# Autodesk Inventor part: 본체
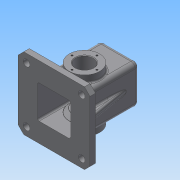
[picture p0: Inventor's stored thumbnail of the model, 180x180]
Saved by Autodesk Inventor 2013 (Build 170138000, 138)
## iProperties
Created: 2016-02
Part Number: 본체
Material: Generic
Document SubType Name: Modeling
Designer: Administrator
Density: 1 g/cm^3
Author: Administrator
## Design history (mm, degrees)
sketch "스케치1"
  geometry: L1 (-35, -35)-(35, -35); L2 (35, -35)-(35, 35); L3 (35, 35)-(-35, 35); L4 (-35, 35)-(-35, -35); L5 (-35, -35)-(35, 35); L6 (35, -35)-(-35, 35); 1 further point
  constraints: 12 end point, 2 midpoint, 2 parallel, 2 perpendicular, 1 horizontal
  dimensions: "d0" = 70 distance of L2.end L3.end
extrude "돌출1" new body sketch "스케치1" distance "d2" = 120; taper "d3" = 0 deg
fillet "모깎기1" dims "d5" = 8
fillet "모깎기2" dims "d6" = 8
feature "쉘1" dims "d7" = 5
sketch "스케치2"
  geometry: L1 (-65, -65)-(65, -65); L2 (65, -65)-(65, 65); L3 (65, 65)-(-65, 65); L4 (-65, 65)-(-65, -65); L5 (-65, -65)-(65, 65); L6 (65, -65)-(-65, 65); L7 (30, -27)-(30, 27) reference; L8 (27, 30)-(-27, 30) reference; L9 (-30, 27)-(-30, -27) reference; L10 (-27, -30)-(27, -30) reference; L11 (27, -35)-(-27, -35) reference; L12 (-35, -27)-(-35, 27) reference; L13 (-27, 35)-(27, 35) reference; L14 (35, 27)-(35, -27) reference; A1 r 3 centre (27, -27) between (27, -30) and (30, -27) reference; A2 r 3 centre (27, 27) between (30, 27) and (27, 30) reference; A3 r 3 centre (-27, 27) between (-27, 30) and (-30, 27) reference; A4 r 3 centre (-27, -27) between (-30, -27) and (-27, -30) reference; A5 r 8 centre (27, -27) between (27, -35) and (35, -27) reference; A6 r 8 centre (-27, -27) between (-35, -27) and (-27, -35) reference; A7 r 8 centre (-27, 27) between (-27, 35) and (-35, 27) reference; A8 r 8 centre (27, 27) between (35, 27) and (27, 35) reference; 1 further point
  constraints: 12 end point, 2 midpoint, 2 parallel, 2 perpendicular, 1 horizontal
  dimensions: "d8" = 130 distance of L2.end L3.end
extrude "돌출2" join sketch "스케치2" distance "d10" = 10; taper "d11" = 0 deg
sketch "스케치3"
  geometry: L1 (65, 65)-(-65, 65) reference; L2 (65, -65)-(65, 65) reference; 3 further points
  constraints: 1 vertical alignment
  dimensions: "d12" = 100 distance of point (50, 50) point (50, -50); "d14" = 15 distance from line of L1 point (50, 50); "d15" = 15 distance from line of point (50, 50) L2
hole "구멍1" sketch "스케치3" at (50, -50), (50, 50) diameter "d16" = 12; stored, may be unused: countersink angle "d20" = 90 deg, drill point angle "d22" = 0 deg; dims "d17" = 6, "d18" = 4, "d19" = 2, "d21" = 8
chamfer "모따기1" distance "d23" = 10; stored, may be unused: second distance "d24" = 2, angle "d25" = 45 deg
node "작업 평면1"
sketch "스케치5"
  geometry: L1 (-27, 0)-(27, 0) reference; C1 r 27.5 at (0, 55); 1 further point
  constraints: 1 centre point, 1 midpoint, 1 vertical alignment
  dimensions: "d26" = 55 diameter of C1; "d29" = 55 distance of point (0, 0) C1.centre
extrude "돌출3" join sketch "스케치5" stored distance "d30" = 10; taper "d31" = 0 deg
sketch "스케치6"
  geometry: C1 r 27.5 at (27, 55) reference; C2 r 27.5 at (27, 55); 1 further point
  constraints: 1 centre point, 1 coincident
  dimensions: "d32" = 55 diameter of C2
extrude "돌출4" join sketch "스케치6" distance "d33" = 7; taper "d34" = -45 deg
hole "구멍2" diameter "d37" = 32; stored, may be unused: countersink angle "d41" = 90 deg, drill point angle "d43" = 0 deg; dims "d35" = 10, "d36" = 10, "d38" = 6, "d39" = 4, "d40" = 2, "d42" = 8
sketch "스케치7"
  geometry: C1 r 16 at (0, 0) reference; 2 further points
  constraints: 1 vertical alignment
  dimensions: "d44" = 22.5 distance of C1.centre point (0, 22.5)
hole "구멍3" sketch "스케치7" at (0, 22.5) diameter "d45" = 3.242; stored, may be unused: countersink angle "d49" = 90 deg, drill point angle "d51" = 118 deg; dims "d46" = 8, "d47" = 4, "d48" = 2, "d50" = 10
sketch "스케치8"
  geometry: C1 r 20 at (0, 0); 1 further point
  constraints: 1 centre point, 1 coincident
  dimensions: "d56" = 40 diameter of C1
extrude "돌출5" join sketch "스케치8" distance "d57" = 10; taper "d58" = -10 deg
hole "구멍4" diameter "d61" = 21; stored, may be unused: countersink angle "d65" = 90 deg, drill point angle "d67" = 0 deg; dims "d59" = 10, "d60" = 10, "d62" = 8, "d63" = 28, "d64" = 4, "d66" = 10
chamfer "모따기2" distance "d68" = 1; stored, may be unused: second distance "d69" = 2, angle "d70" = 45 deg
sketch "스케치9"
  geometry: L1 (27, 115)-(10.5, 115) reference; L2 (10.5, 115)-(10.5, 126) reference; L3 (10.5, 126)-(14, 126) reference; L4 (14, 126)-(14, 130) reference; L5 (14, 130)-(18.237, 130) reference; L6 (18.237, 130)-(20, 120) reference; L7 (20, 120)-(27, 120) reference; L8 (35, 112)-(35, 10) reference; L9 (35, 10)-(65, 10) reference; L10 (65, 10)-(65, 0) reference; L11 (65, 0)-(30, 0) reference; L12 (30, 0)-(30, 112) reference; L13 (-27, 120)-(-20, 120) reference; L14 (-20, 120)-(-18.237, 130) reference; L15 (-18.237, 130)-(-14, 130) reference; L16 (-14, 130)-(-14, 126) reference; L17 (-14, 126)-(-10.5, 126) reference; L18 (-10.5, 126)-(-10.5, 115) reference; L19 (-10.5, 115)-(-27, 115) reference; L20 (-30, 112)-(-30, 0) reference; L21 (-30, 0)-(-65, 0) reference; L22 (-65, 0)-(-65, 10) reference; L23 (-65, 10)-(-35, 10) reference; L24 (-35, 10)-(-35, 112) reference; L25 (35, 95.069)-(50, 10); A1 r 3 centre (27, 112) between (30, 112) and (27, 115) reference; A2 r 8 centre (27, 112) between (35, 112) and (27, 120) reference; A3 r 8 centre (-27, 112) between (-27, 120) and (-35, 112) reference; A4 r 3 centre (-27, 112) between (-27, 115) and (-30, 112) reference; 1 further point
  constraints: 2 end point, 1 midpoint, 1 point on line
  dimensions: "d71" = 10 deg angle of L10 L25; "d72" = 15 distance from line of L10 L25.end
feature "리브1" sketch "스케치9" dims "d73" = 1, "d74" = 10, "d75" = 0, "d76" = 0, "d77" = 1, "d78" = 1
sketch "스케치10"
  geometry: L1 (8.763, 18)-(45.237, 18) reference; A1 r 27.5 centre (27, -57) between (54, -51.78) and (0, -51.78) reference; 2 further points
  constraints: 1 vertical alignment, 1 other
  dimensions: "d79" = 30 distance from line of point (27, -12) L1
feature "엠보싱1" sketch "스케치10" dims "d0" = 70, "d80" = 0.5, "d81" = 0
fillet "모깎기3" dims "d82" = 0.5, "d83" = 3
fillet "모깎기5" dims "d85" = 3
fillet "모깎기6" dims "d86" = 3
fillet "모깎기7" dims "d87" = 3
node "솔리드1"
mirror "대칭1"
pattern_circular "원형 패턴1" dims angle "d53" = 360 deg
mirror "대칭2"
mirror "대칭3"
node "투영된 루프1"
node "절단 모서리 투영1"
node "절단 모서리 투영2"
other parameters: "d28" = 48
